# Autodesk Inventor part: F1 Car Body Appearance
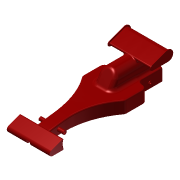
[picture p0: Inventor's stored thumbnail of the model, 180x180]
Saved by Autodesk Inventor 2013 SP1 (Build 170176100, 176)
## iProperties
Created: 2013-01
Part Number: F1 Car Body Appearance
Material: Generic
Document SubType Name: Modeling
Designer: banachd
Density: 0.55 g/cm^3
Mass: 113.444 g
Surface Area: 400.752 cm^2
Volume: 206.262 cm^3
Description: CAR BODY
Author: banachd
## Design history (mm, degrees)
sketch "Sketch1"
  geometry: L1 (0, 0)-(200, 0); L2 (200, 0)-(200, 20); L3 (200, 20)-(110, 20); L4 (0, 8)-(0, 0); A1 r 510.167 centre (110, -490.167) between (110, 20) and (0, 8)
  constraints: 8 end point, 2 perpendicular, 2 point on circle, 1 centre point, 1 horizontal, 1 parallel, 1 tangent
  dimensions: "d0" = 200 distance of L1.start L1.end; "d1" = 20 distance of L1.end L2.end; "d2" = 90 distance of L2.end L3.end; "d3" = 8 distance of L4.start L1.start
extrude "Extrusion1" new body sketch "Sketch1" distance "d4" = 35; taper "d5" = 0 deg
sketch "Sketch2"
  geometry: L1 (0, 0)-(200, 0) reference; L2 (0, 35)-(200, 35) reference; L3 (0, 0)-(0, 35) reference; L4 (0, 10)-(50, 10); L5 (200, 35)-(160, 35); L6 (160, 35)-(160, 19); L7 (160, 19)-(200, 19); L8 (200, 19)-(200, 35); A1 r 120 centre (50, 130) between (50, 10) and (123.314, 35)
  constraints: 10 end point, 3 parallel, 2 point on circle, 2 point on line, 1 centre point, 1 horizontal, 1 perpendicular, 1 tangent
  dimensions: "d6" = 50 distance of L4.start L4.end; "d7" = 40 distance of L7.end L6.end; "d8" = 16 distance of L6.end L5.end; "d9" = 10 distance between parallel lines of L4 L1; "d10" = 120 radius of A1
extrude "Extrusion2" cut sketch "Sketch2" stored distance "d11" = 0; taper "d12" = 0 deg
sketch "Sketch3"
  geometry: L1 (0, 0)-(0, 8) reference; L2 (50, 0)-(0, 0) reference; C1 r 3 at (40, 8)
  constraints: 1 centre point
  dimensions: "d13" = 6 diameter of C1; "d15" = 8 distance from line of C1.centre L2; "d17" = 40 distance from line of C1.centre L1
extrude "Extrusion3" join sketch "Sketch3" distance "d18" = 10; taper "d19" = 0 deg
hole "Hole1" diameter "d22" = 3; stored, may be unused: countersink angle "d26" = 90 deg, drill point angle "d28" = 118 deg; dims "d20" = 10, "d21" = 10, "d23" = 6, "d24" = 4, "d25" = 2, "d27" = 8
pattern_linear "Rectangular Pattern1"
fillet "Fillet1" dims "d32" = 8
mirror "Mirror1"
sketch "Sketch4"
  geometry: L1 (38, 20)-(0, 20) reference; L2 (5, 20)-(5, 30); L3 (33, 30)-(33, 20); L4 (-8, 0)-(-16, 0) reference; A1 r 14 centre (19, 30) between (33, 30) and (5, 30); 2 further points
  constraints: 4 end point, 2 perpendicular, 2 point on circle, 2 point on line, 2 tangent, 1 centre point, 1 midpoint, 1 vertical alignment
  dimensions: "d33" = 30 distance from line of A1.centre L4; "d34" = 14 radius of A1
extrude "Extrusion4" join sketch "Sketch4" distance "d35" = 80; taper "d36" = 0 deg
sketch "Sketch5"
  geometry: L1 (0, 0)-(0, 8) reference; L2 (110, 20)-(120, 20) reference; L3 (120, 20)-(120, 44) reference; L4 (120, 44)-(200, 44) reference; L5 (200, 44)-(200, 0) reference; L6 (200, 0)-(0, 0) reference; L7 (0, 8)-(25.066, 17.123); L8 (168.592, 41)-(193.592, 41); L9 (191.4, 53.43)-(167.908, 44.879); C1 r 1.5 at (180, 8) reference; C2 r 1.5 at (40, 8) reference; A1 r 510.167 centre (110, -490.167) between (110, 20) and (0, 8) reference; A2 r 17.5 centre (40, 8) between (25.066, 17.123) and (24.436, 0); A3 r 6.408 centre (193.592, 47.408) between (193.592, 41) and (191.4, 53.43); A4 r 2 centre (168.592, 43) between (167.908, 44.879) and (168.592, 41)
  constraints: 6 end point, 6 point on circle, 5 tangent, 3 centre point, 1 coincident, 1 parallel, 1 point on line
  dimensions: "d37" = 17.5 radius of A2; "d38" = 25 distance of L8.start L8.end; "d39" = 2 radius of A4; "d40" = 20 deg angle of L8 L9; "d41" = 20 deg angle of L6 L7; "d42" = 3 distance between parallel lines of L8 L4
  node "Project Cut Edges1"
extrude "Extrusion5" join sketch "Sketch5" stored distance "d43" = 70; taper "d44" = 0 deg
extrude "Extrusion6" join sketch "Sketch5" stored distance "d45" = 70; taper "d46" = 0 deg
hole "Hole2" diameter "d49" = 19.5; stored, may be unused: countersink angle "d53" = 90 deg, drill point angle "d55" = 118 deg; dims "d47" = 10, "d48" = 10, "d50" = 6, "d51" = 4, "d52" = 2, "d54" = 55
sketch "Sketch8"
  geometry: L1 (0, 8)-(25.066, 17.123) reference; L2 (110, 20)-(120, 20) reference; L3 (120, 20)-(120, 44) reference; L4 (120, 44)-(166.86, 44) reference; L5 (167.908, 44.879)-(191.4, 53.43) reference; L6 (199.019, 44)-(200, 44) reference; L7 (200, 44)-(200, 39.75) reference; L8 (200, 39.75)-(145, 39.75) reference; L9 (145, 39.75)-(139.142, 30) reference; L10 (139.142, 30)-(145, 20.25) reference; L11 (145, 20.25)-(200, 20.25) reference; L12 (200, 20.25)-(200, 0) reference; L13 (200, 0)-(0, 0) reference; L14 (0, 0)-(0, 8) reference; L15 (120, 20)-(133.856, 44); C1 r 1.5 at (180, 8) reference; C2 r 1.5 at (40, 8) reference; A1 r 17.5 centre (40, 8) between (25.066, 17.123) and (23.1, 12.544) reference; A2 r 510.167 centre (110, -490.167) between (110, 20) and (23.1, 12.544) reference; A3 r 2 centre (168.592, 43) between (167.908, 44.879) and (166.86, 44) reference; A4 r 6.408 centre (193.592, 47.408) between (199.019, 44) and (191.4, 53.43) reference
  constraints: 2 end point, 1 point on line
  dimensions: "d80" = 30 deg angle of L15 L3
extrude "Extrusion8" cut sketch "Sketch8" stored distance "d81" = 10; taper "d82" = 0 deg
sketch "Sketch6"
  geometry: L1 (168.592, 41)-(193.592, 41) reference; L2 (191.4, 53.43)-(167.908, 44.879) reference; L3 (167.224, 46.759)-(190.716, 55.309); L4 (193.592, 39)-(168.592, 39); A1 r 6.408 centre (193.592, 47.408) between (193.592, 41) and (191.4, 53.43) reference; A2 r 2 centre (168.592, 43) between (167.908, 44.879) and (168.592, 41) reference; A3 r 8.408 centre (193.592, 47.408) between (193.592, 39) and (190.716, 55.309); A4 r 4 centre (168.592, 43) between (167.224, 46.759) and (168.592, 39); 1 further point
  constraints: 4 end point, 4 point on circle, 2 centre point, 3 other
  dimensions: "d56" = 2 distance between parallel lines of L3 L2
extrude "Extrusion7" join sketch "Sketch6" distance "d57" = 1; taper "d58" = 0 deg
mirror "Mirror2"
fillet "Fillet2"
fillet "Fillet3" dims "d59" = 2
fillet "Fillet4" dims "d60" = 7
sketch "Sketch9"
  geometry: L1 (38, 0)-(0, 0) reference; L2 (16, 6)-(22, 6); L3 (22, 6)-(22, 0); L4 (22, 0)-(16, 0); L5 (16, 0)-(16, 6); 2 further points
  constraints: 8 end point, 2 midpoint, 2 parallel, 1 horizontal, 1 perpendicular
  dimensions: "d83" = 6 distance of L3.end L4.end; "d84" = 6 distance of L2.end L3.end
extrude "Extrusion9" cut sketch "Sketch9" stored distance "d85" = 10; taper "d86" = 0 deg
body "Solid1"
node "Project Cut Edges2"
